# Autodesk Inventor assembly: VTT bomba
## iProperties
Created: 2006-03
Part Number: VTT bomba
Document SubType Name: Assembly
Designer: Flavien MARTY
Norme de conversion: STEP AP214DIS
Nom du fichier: bomba avec roue arr.STEP
Préprocesseur: SolidWorks 2005204
Postprocesseur: Build: 272, Release: 10 SP3a - Date: Thu 12/15/2005
Unités envoyées: MILLIMETERS
Incertitude: 1e-05
Author: Flavien MARTY
